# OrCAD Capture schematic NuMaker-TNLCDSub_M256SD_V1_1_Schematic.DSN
size B; title: LCD Connector; rev: v1.1; note: NuMaker-TNLCDSub_M256SD V1.1
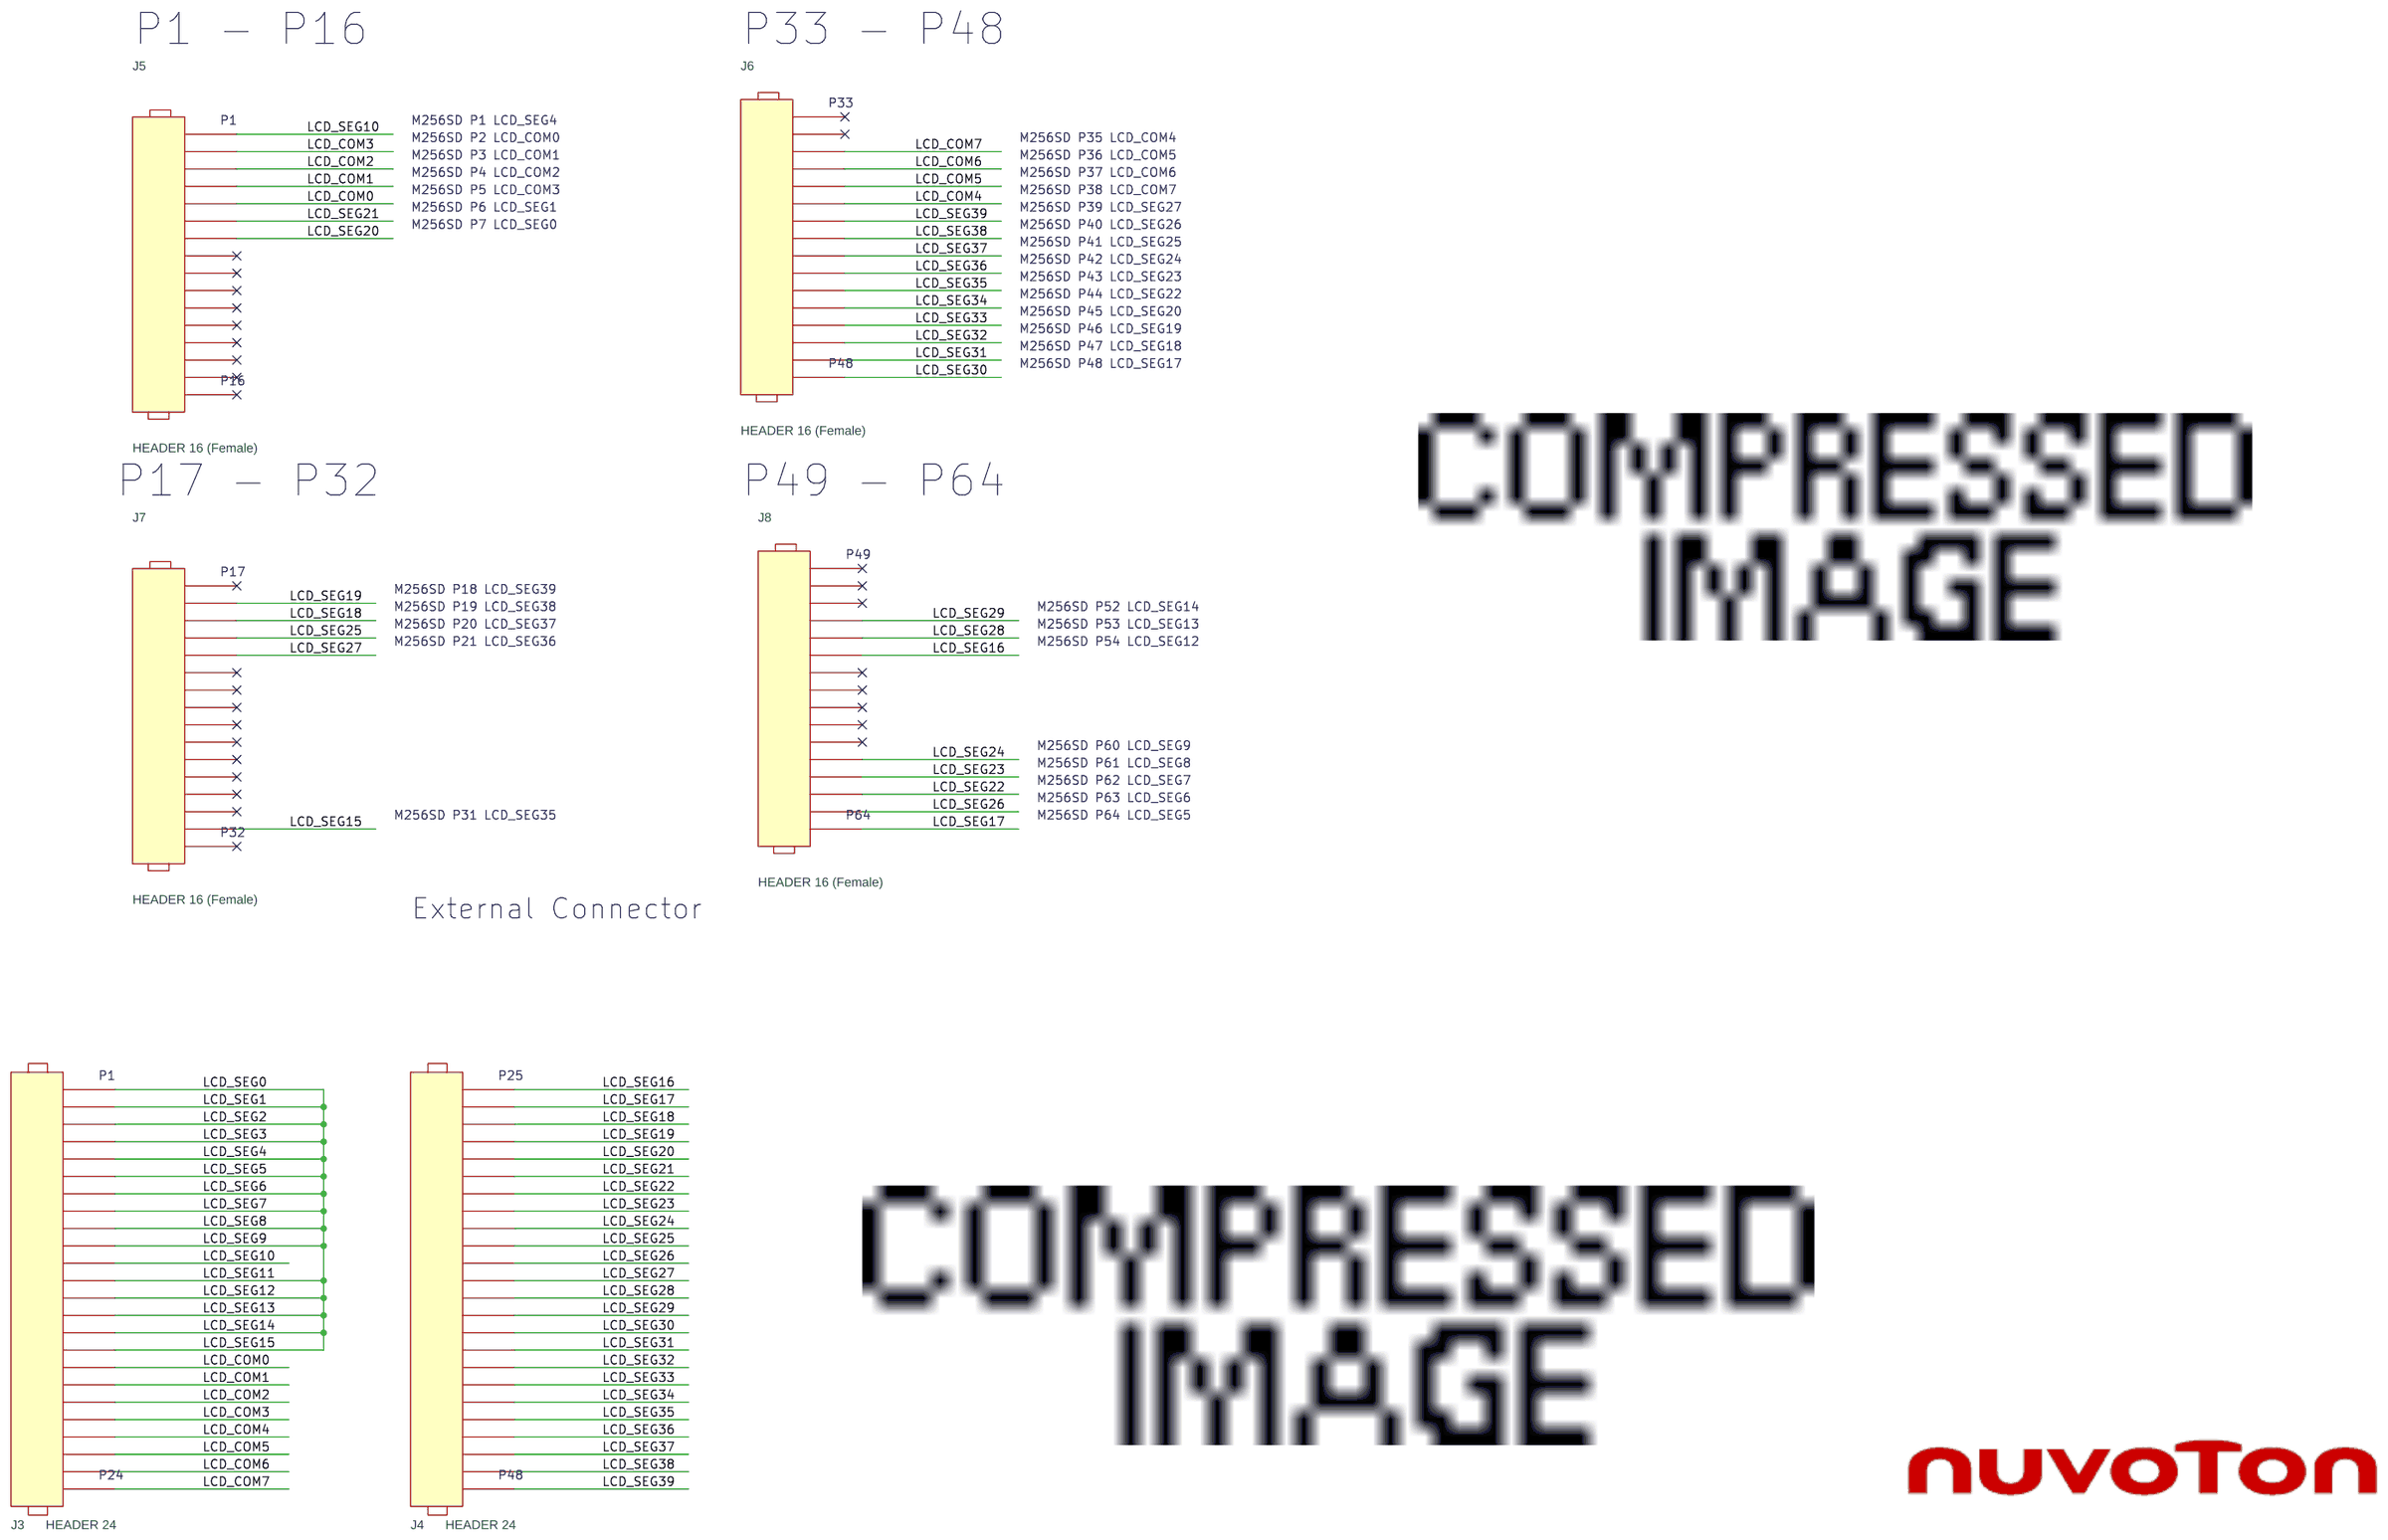
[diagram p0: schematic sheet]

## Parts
J3  HEADER 24  [HEADER24]
J4  HEADER 24  [HEADER24]
J5  HEADER 16 (Female)  [HEADER16]
J6  HEADER 16 (Female)  [HEADER16]
J7  HEADER 16 (Female)  [HEADER16]
J8  HEADER 16 (Female)  [HEADER16]

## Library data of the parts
J3 J4 = HEADER_24
J5-J8 = HEADER_16

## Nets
LCD_COM0: J3.17 J5.5
LCD_COM1: J3.18 J5.4
LCD_COM2: J3.19 J5.3
LCD_COM3: J3.20 J5.2
LCD_COM4: J3.21 J6.6
LCD_COM5: J3.22 J6.5
LCD_COM6: J3.23 J6.4
LCD_COM7: J3.24 J6.3
LCD_SEG0: J3.1 J3.2 J3.3 J3.4 J3.5 J3.6 J3.7 J3.8 J3.9 J3.10 J3.12 J3.13 J3.14 J3.15 J3.16 J7.15
LCD_SEG10: J3.11 J5.1
LCD_SEG16: J4.1 J8.6
LCD_SEG17: J4.2 J8.16
LCD_SEG18: J4.3 J7.3
LCD_SEG19: J4.4 J7.2
LCD_SEG20: J4.5 J5.7
LCD_SEG21: J4.6 J5.6
LCD_SEG22: J4.7 J8.14
LCD_SEG23: J4.8 J8.13
LCD_SEG24: J4.9 J8.12
LCD_SEG25: J4.10 J7.4
LCD_SEG26: J4.11 J8.15
LCD_SEG27: J4.12 J7.5
LCD_SEG28: J4.13 J8.5
LCD_SEG29: J4.14 J8.4
LCD_SEG30: J4.15 J6.16
LCD_SEG31: J4.16 J6.15
LCD_SEG32: J4.17 J6.14
LCD_SEG33: J4.18 J6.13
LCD_SEG34: J4.19 J6.12
LCD_SEG35: J4.20 J6.11
LCD_SEG36: J4.21 J6.10
LCD_SEG37: J4.22 J6.9
LCD_SEG38: J4.23 J6.8
LCD_SEG39: J4.24 J6.7

Not connected (* = marked no-connect by the designer): J5 8* 9* 10* 11* 12* 13* 14* 15* 16*; J6 1* 2*; J7 1* 6* 7* 8* 9* 10* 11* 12* 13* 14* 16*; J8 1* 2* 3* 7* 8* 9* 10* 11*

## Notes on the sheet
- P1 - P16
- P33 - P48
- P33
- P1
- M256SD P1 LCD_SEG4
- M256SD P2 LCD_COM0
- M256SD P35 LCD_COM4
- M256SD P3 LCD_COM1
- M256SD P36 LCD_COM5
- M256SD P4 LCD_COM2
- M256SD P37 LCD_COM6
- M256SD P5 LCD_COM3
- M256SD P6 LCD_SEG1
- M256SD P38 LCD_COM7
- M256SD P39 LCD_SEG27
- M256SD P7 LCD_SEG0
- M256SD P40 LCD_SEG26
- M256SD P41 LCD_SEG25
- M256SD P42 LCD_SEG24
- M256SD P43 LCD_SEG23
- M256SD P44 LCD_SEG22
- M256SD P45 LCD_SEG20
- M256SD P46 LCD_SEG19
- M256SD P47 LCD_SEG18
- P48
- M256SD P48 LCD_SEG17
- P16
- P17 - P32
- P49 - P64
- P49
- P17
- M256SD P18 LCD_SEG39
- M256SD P19 LCD_SEG38
- M256SD P52 LCD_SEG14
- M256SD P20 LCD_SEG37
- M256SD P53 LCD_SEG13
- M256SD P21 LCD_SEG36
- M256SD P54 LCD_SEG12
- M256SD P60 LCD_SEG9
- M256SD P61 LCD_SEG8
- M256SD P62 LCD_SEG7
- M256SD P63 LCD_SEG6
- M256SD P31 LCD_SEG35
- P64
- M256SD P64 LCD_SEG5
- P32
- External Connector
- P1
- P25
- P24
- P48
